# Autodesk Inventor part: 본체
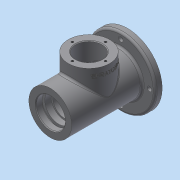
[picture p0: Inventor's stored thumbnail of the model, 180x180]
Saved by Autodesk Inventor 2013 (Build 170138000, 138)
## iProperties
Created: 2016-08
Part Number: 본체
Material: 일반
Document SubType Name: Modeling
Designer: dgall
Density: 1 g/cm^3
Author: dgall
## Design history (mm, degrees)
sketch "스케치1"
  geometry: C1 r 50 at (0, 0); 1 further point
  constraints: 1 centre point, 1 coincident
  dimensions: "d0" = 100 diameter of C1
extrude "돌출1" new body sketch "스케치1" distance "d2" = 10; taper "d3" = 0 deg
sketch "스케치2"
  geometry: C1 r 50 at (0, 0) reference; C2 r 31 at (0, 0)
  constraints: 1 centre point, 1 coincident
  dimensions: "d4" = 62 diameter of C2
extrude "돌출2" join sketch "스케치2" distance "d6" = 3; taper "d7" = 0 deg
sketch "스케치3"
  geometry: C1 r 50 at (0, 0) reference; C2 r 31 at (0, 0)
  constraints: 1 centre point, 1 coincident
  dimensions: "d8" = 62 diameter of C2
extrude "돌출3" join sketch "스케치3" distance "d10" = 102; taper "d11" = 0 deg
fillet "모깎기1" dims "d12" = 3
fillet "모깎기2" dims "d13" = 3
sketch "스케치4" dims "d14" = 83
  geometry: C1 r 31 at (0, 0) reference; C2 r 50 at (0, 0) reference; C3 r 4 at (0, 41.5); 1 further point
  constraints: 2 vertical alignment, 1 centre point, 1 coincident, 2 other
  dimensions: "d16" = 8 diameter of C3
hole "구멍1" sketch "스케치4" at (0, 41.5) diameter "d17" = 6.647; stored, may be unused: countersink angle "d21" = 90 deg, drill point angle "d23" = 118 deg; dims "d18" = 6, "d19" = 4, "d20" = 2, "d22" = 8
node "작업 평면1"
sketch "스케치5"
  geometry: L1 (-31, -102)-(31, -102) reference; C1 r 30 at (0, -46); 1 further point
  constraints: 1 centre point
  dimensions: "d28" = 0 horizontal distance of point (0, 0) C1.centre; "d29" = 56 distance from line of C1.centre L1; "d30" = 60 diameter of C1
extrude "돌출4" join sketch "스케치5" stored distance "d31" = 102; taper "d32" = 0 deg
fillet "모깎기3" dims "d33" = 3
sketch "스케치6"
  geometry: C1 r 31 at (0, 0) reference; C2 r 21 at (0, 0)
  constraints: 1 centre point, 1 coincident
  dimensions: "d34" = 42 diameter of C2
extrude "돌출5" cut sketch "스케치6" distance "d36" = 14; taper "d37" = 0 deg
sketch "스케치7"
  geometry: C1 r 31 at (0, 0) reference; C2 r 21 at (0, 0)
  constraints: 1 centre point, 1 coincident
  dimensions: "d38" = 42 diameter of C2
extrude "돌출6" cut sketch "스케치7" distance "d40" = 9; taper "d41" = 0 deg
chamfer "모따기1" distance "d42" = 1; stored, may be unused: second distance "d43" = 2, angle "d44" = 45 deg
sketch "스케치8"
  geometry: C1 r 21 at (0, 0) reference; C2 r 12.5 at (0, 0)
  constraints: 1 centre point, 1 coincident
  dimensions: "d45" = 25 diameter of C2
extrude "돌출7" cut sketch "스케치8" distance "d47" = 0.7; taper "d48" = -30 deg
fillet "모깎기4" dims "d49" = 3
sketch "스케치9"
  geometry: C1 r 12.096 at (0, 0) reference; C2 r 12.5 at (0, 0)
  constraints: 1 centre point, 1 coincident
  dimensions: "d50" = 25 diameter of C2
extrude "돌출8" cut sketch "스케치9" distance "d52" = 6.6; taper "d53" = 0 deg
sketch "스케치10"
  geometry: C1 r 12.096 at (0, 0) reference; C2 r 10 at (0, 0)
  constraints: 1 centre point, 1 coincident
  dimensions: "d54" = 20 diameter of C2
extrude "돌출9" cut sketch "스케치10" distance "d56" = 2.7; taper "d57" = 0 deg
fillet "모깎기5" dims "d58" = 0.3
sketch "스케치11"
  geometry: C1 r 10 at (0, 0) reference; C2 r 16.5 at (0, 0)
  constraints: 1 centre point, 1 coincident
  dimensions: "d59" = 33 diameter of C2
extrude "돌출10" cut sketch "스케치11" distance "d61" = 10; taper "d62" = 0 deg
sketch "스케치12"
  geometry: C1 r 10 at (0, 0) reference
extrude "돌출11" cut sketch "스케치12" distance "d63" = 10; taper "d64" = 0 deg
sketch "스케치13"
  geometry: C1 r 30 at (0, 0) reference; C2 r 2 at (-24, 0); C3 r 2 at (0, -24); C4 r 2 at (24, 0); C5 r 2 at (0, 24); A1 r 24 centre (0, 0) between (-24, 0) and (0, -24); 1 further point
  constraints: 5 centre point, 4 point on circle, 2 horizontal alignment, 2 vertical alignment, 1 coincident
  dimensions: "d65" = 48 diameter of A1; "d67" = 4 diameter of C2; "d68" = 4 diameter of C3; "d69" = 4 diameter of C4; "d70" = 4 diameter of C5
hole "구멍2" sketch "스케치13" at (0, -24), (24, 0), (-24, 0), (0, 24) diameter "d71" = 3.242; stored, may be unused: countersink angle "d75" = 90 deg, drill point angle "d77" = 118 deg; dims "d72" = 8, "d73" = 4, "d74" = 2, "d76" = 10
sketch "스케치14"
  geometry: C1 r 21 at (0, 0) reference; C2 r 24 at (0, 0)
  constraints: 1 centre point, 1 coincident
  dimensions: "d78" = 48 diameter of C2
extrude "돌출12" cut sketch "스케치14" distance "d80" = 3; taper "d81" = 0 deg
sketch "스케치15"
  geometry: C1 r 21 at (0, 0) reference
extrude "돌출13" cut sketch "스케치15" distance "d82" = 3; taper "d83" = 0 deg
sketch "스케치16"
  geometry: C1 r 24 at (0, 0) reference; C2 r 20 at (0, 0)
  constraints: 1 centre point, 1 coincident
  dimensions: "d84" = 40 diameter of C2
extrude "돌출14" cut sketch "스케치16" distance "d86" = 9; taper "d87" = 0 deg
sketch "스케치17"
  geometry: C1 r 20 at (0, 0) reference; C2 r 17.5 at (0, 0)
  constraints: 1 centre point, 1 coincident
  dimensions: "d88" = 35 diameter of C2
extrude "돌출15" cut sketch "스케치17" distance "d90" = 24.25; taper "d91" = 0 deg
sketch "스케치18"
  geometry: C1 r 17.5 at (0, 0) reference; C2 r 18.5 at (0, 0)
  constraints: 1 centre point, 1 coincident
  dimensions: "d92" = 37 diameter of C2
extrude "돌출16" cut sketch "스케치18" distance "d94" = 1.75; taper "d95" = 0 deg
sketch "스케치20"
  geometry: C1 r 17.5 at (0, 0) reference; C2 r 17.5 at (0, 0)
  constraints: 1 centre point, 1 coincident
  dimensions: "d96" = 35 diameter of C2
extrude "돌출17" cut sketch "스케치20" distance "d98" = 1.75; taper "d99" = 0 deg
sketch "스케치21"
  geometry: C1 r 18.5 at (0, 0) reference; C2 r 26 at (0, 0)
  constraints: 1 centre point, 1 coincident
  dimensions: "d100" = 52 diameter of C2
extrude "돌출18" cut sketch "스케치21" distance "d101" = 38; taper "d102" = 0 deg
sketch "스케치22"
  geometry: C1 r 18.5 at (0, 0) reference
extrude "돌출19" cut sketch "스케치22" distance "d103" = 38; taper "d104" = 0 deg
sketch "스케치23"
  geometry: C1 r 30 at (0, 0) reference; C2 r 19 at (0, 0); 1 further point
  constraints: 1 centre point, 1 coincident
  dimensions: "d105" = 38 diameter of C2
extrude "돌출20" cut sketch "스케치23" stored distance "d107" = 38; taper "d108" = 0 deg
chamfer "모따기2" distance "d109" = 1; stored, may be unused: second distance "d110" = 2, angle "d111" = 45 deg
node "작업 평면2"
sketch "스케치25"
  geometry: L1 (-66.739, 42.002)-(-25.261, 42.002); L2 (-25.261, 42.002)-(-25.261, 35.998); L3 (-25.261, 35.998)-(-66.739, 35.998); L4 (-66.739, 35.998)-(-66.739, 42.002); L5 (-66.739, 39)-(-25.261, 39); L6 (-46, 42.002)-(-46, 35.998); L7 (-76, 49)-(-16, 49) reference; L8 (-102, 31)-(-102, -31) reference; 1 further point
  constraints: 4 end point, 4 midpoint, 2 other
  dimensions: "d113" = 10 distance from line of L5.end L7; "d114" = 56 distance between parallel lines of L6 L8
feature "엠보싱1" sketch "스케치25" dims "d0" = 100, "d115" = 0.5, "d116" = 0
fillet "모깎기6" dims "d117" = 3
node "솔리드1"
pattern_circular "원형 패턴1" dims angle "d25" = 360 deg
other parameters: "d27" = 49, "d112" = 51.5
